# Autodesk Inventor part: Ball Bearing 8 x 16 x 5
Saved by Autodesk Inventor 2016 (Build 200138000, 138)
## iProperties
Created: 2015-11
Part Number: Ball Bearing 8 x 16 x 5
Material: Generic
Document SubType Name: Modeling
Designer: John
Density: 1 g/cm^3
Appearance: Default
Author: John
Revision Number: ANY
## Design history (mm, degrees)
feature "Revolve1"
body "Solid1"
